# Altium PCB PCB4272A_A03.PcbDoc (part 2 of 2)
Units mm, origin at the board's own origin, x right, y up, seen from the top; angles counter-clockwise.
Board outline 32 x 51 mm, 4 copper layers (Top Layer, Signal Layer 2, Signal Layer 3, Bottom Layer), stack 1.6 mm thick; 110 components, 91 nets, 408 pads, 551 vias.
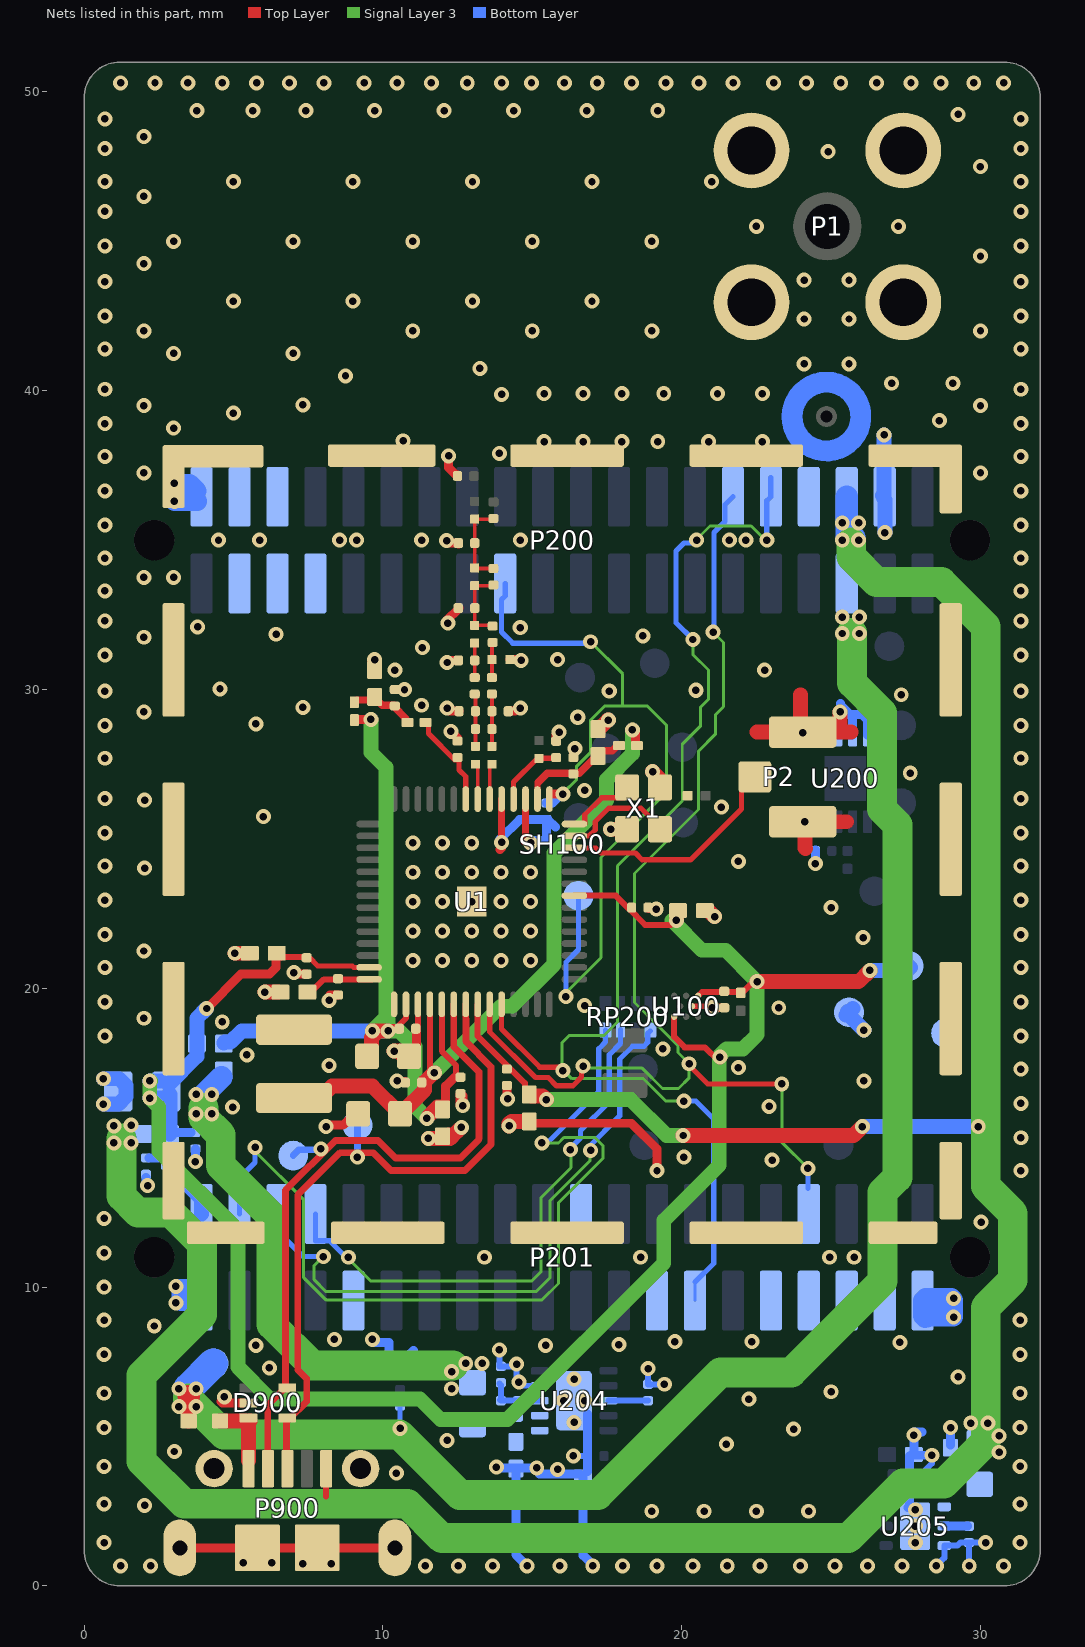
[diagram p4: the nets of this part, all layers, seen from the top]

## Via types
v1: diameter 0.5, hole 0.25, Top Layer to Bottom Layer, tented both sides, 512 vias
v2: diameter 0.508, hole 0.25, Top Layer to Bottom Layer, tented both sides, 37 vias
v3: diameter 0.5/0/0/0.5 (per signal layer), hole 0.25, Top Layer to Bottom Layer, tented both sides, 2 vias

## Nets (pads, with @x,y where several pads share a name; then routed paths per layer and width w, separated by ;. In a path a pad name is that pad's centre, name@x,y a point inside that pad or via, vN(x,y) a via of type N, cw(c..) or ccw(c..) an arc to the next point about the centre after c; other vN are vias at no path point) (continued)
EFR32_PD04: P200.32 P201.27 U1.52 | length 41.7
  Top Layer w0.175: U1.52@13.975,19.465 13.975,18.64 15.253,17.363 v1@15.875,17.363
  Signal Layer 3 w0.1: v1@15.875,17.275 16,17.4 16,18.191 16.234,18.425 17.4,18.425 17.85,18.875 17.85,24.1 20.02,26.27 20.02,28.165 20.625,28.77 20.625,29.4 20.9,29.675 20.9,30.65 20.375,31.175 v2@20.375,31.6 ; v1(16.025,17.25) 16.05,17.25 16.325,16.975 18.725,16.975 19.474,16.226 v2(20.076,16.226) ; v2@20.35,31.675 v2@20.4,31.625 ; v2@20.5,35.025 20.95,35.475 22.325,35.475 22.838,34.963 22.877,35.002 v2(22.851,35.002)
  Bottom Layer w0.1: P201.27@20.445,9.55 P201.27@20.445,10.17
  Bottom Layer w0.175: v2(20.076,16.226) 20.474,16.226 21.075,15.625 ; v2(20.375,31.675) 19.813,32.237 19.813,34.638 20.075,34.9 20.4,34.9 v2(20.5,35) ; P201.27@20.445,10.17 21.078,10.803 21.078,15.625 ; v2@22.975,35.1 22.85,35.1 22.85,36.315 P200.32@22.985,36.45 P200.32@22.985,37.09
EFR32_PD05: P200.30 P201.34 U1.51 | length 38.4
  Top Layer w0.175: U1.51@13.575,19.465 13.575,18.545 15.108,17.013 15.537,17.013 15.812,16.738 16.357,16.738 16.65,17.03 v1@16.65,17.3 ; v1@20.2,17.475 20.875,16.8 v1(23.35,16.8)
  Signal Layer 3 w0.1: v1@16.575,17.35 16.597,17.328 18.678,17.328 19.355,16.651 19.894,16.651 20.251,17.008 v1(20.251,17.476) 19.875,17.852 19.875,18.075 18.421,19.529 18.421,23.846 20.56,25.985 20.56,27.935 21.125,28.5 21.125,29.15 21.4,29.425 21.4,31.575 v2(21.05,31.925) ; v1@23.3,16.75 23.35,16.7 23.35,14.85 v1(24.225,13.975) ; v1@23.3,16.8 v1(23.35,16.8)
  Bottom Layer w0.175: v2@21.083,31.883 21.083,35.258 21.45,35.625 21.45,36.185 P200.30@21.715,36.45 ; v1(24.225,13.975) P201.34@24.228,13.298
  other v1: 16.7,17.4
EFR32_PD06: D900.4 P900.3 TPJ18.1 U1.49 | length 24
  Top Layer w0.22: 12.775,18.9 U1.49@12.775,19.465
  Top Layer w0.23: P900.3@6.845,4.15 6.775,4.22 6.775,5.5 D900.4@6.85,5.575 ; 7.355,6.08 D900.4@6.95,5.675 ; 12.777,18.977 12.777,18.222 13.625,17.374 13.625,14.875 ; 13.624,14.925 13.624,14.777 12.748,13.9 10.277,13.9 9.677,14.5 8.573,14.5 7.15,13.077 7.15,7.25 7.453,6.947 7.453,6.178 D900.4@6.95,5.675 ; D900.4@6.85,5.575 D900.4@6.95,5.675 ; D900.4@6.85,5.575 D900.4@6.95,5.675
  Bottom Layer w0.23: v3(9.15,14.35) TPJ18.1@9.15,15.42
EFR32_PD07: D900.5 P900.2 TPJ19.1 U1.48 | length 22.9
  Top Layer w0.22: 12.375,18.75 U1.48@12.375,19.465
  Top Layer w0.23: P900.2@6.195,4.15 6.15,4.195 6.15,6.05 D900.5@6.725,6.625 ; D900.5@6.745,6.73 6.745,13.245 8.412,14.912 9.838,14.912 10.425,14.325 12.6,14.325 13.2,14.925 ; 12.372,18.962 12.372,18.054 13.219,17.207 13.219,14.975
  Bottom Layer w0.23: TPJ19.1@7,14.4 7.2,14.6 v3@7.85,14.6 ; v3@7.85,14.675 v3@7.925,14.675
  other v3: 7.925,14.625
EFR32_RESET: C207.1 P200.17 TPJ17.1 U1.15 | length 28.3
  Top Layer w0.3: U1.15@15.625,26.5 v2(16.025,26.5)
  Signal Layer 3 w0.1: v2(16.025,26.5) 16.025,26.525 16.487,26.987 16.487,27.433 16.954,27.9 16.954,28.979 17.425,29.45 18.025,29.45 ; v1@16.062,19.788 17.3,21.025 17.3,24.375 19.5,26.575 19.5,28.8 18.85,29.45 18.025,29.45 ; v1(16.95,31.6) 16.95,31.653 16.923,31.627 v1(16.95,31.6) ; v1(16.95,31.6) 18.025,30.525 18.025,29.45
  Bottom Layer w0.175: P200.17@14.095,33.55 14.095,33.13 13.975,33.01 13.975,31.925 14.35,31.55 v1@16.95,31.55 ; v1@16.125,19.75 16.125,20.875 16.55,21.3 TPJ17.1@16.55,23.1
  Bottom Layer w0.3: C207.1@15.475,26.2 15.675,26.2 v2@15.926,26.451
  other v1: 16.125,19.725
GND: C102.2 C103.2 C105.2 C106.2 C107.2 C110.2 C111.2 C112.2 C113.2 C114.2 C115.2 C116.2 C117.2 C118.2 C119.2 C120.2 C121.2 C122.2 C123.2 C124.2 C200.2 C201.2 C203.2 C205.2 C207.2 C253.2 C254.2 C255.2 C257.2 C258.2 C259.2 C260.2 C261.2 CM1.2 CM3.2 CM5.2 CN1.2 CN3.1 CP1.2 CR1.2 D900.2 LP2.1 P1.2 P1.3 P1.4 P1.5 P2.2 P2.3 P200.2 P200.38 P201.1 P201.39 P900.5 P900.6 P900.7 P900.8 P900.9 P900.10 P900.11 R223.1 R246.1 R329.2 SH100.1 TP1.2 TPJ13.1 U1.0 U1.17 U1.19 U1.45 U100.B2 U200.2 U200.3 U200.4 U204.4 U204.11 U205.3 U205.7 X1.2 X1.4 | length 91.9
  Top Layer w0.175: U100.B2@20.35,19.4 U100.B2@20.405,19.399 ; U100.B2@20.405,19.4 20.695,19.4 20.712,19.399 v2@20.875,19.4
  Top Layer w0.2: 8.1,3 P900.5@8.1,3.975 ; C110.2@11.175,18.7 U1.45@11.175,19.465 ; v2@20.875,19.4 v2@20.9,19.375
  Top Layer w0.22: v1@13.961,24.871 v1(13.975,24.886)
  Top Layer w0.23: v1(13.975,24.886) U1.19@13.975,26.335 ; v1@14.775,24.9 U1.17@14.775,26.335
  Top Layer w0.3: P900.8@3.3,1.275 10.125,1.275 P900.9@10.3,1.1 ; v1@4.599,6.2 4.724,6.325 v1(4.7,6.325) ; v1@4.6,6.2 4.575,6.175 4.625,6.125 D900.2@5.5,6.125 ; v1@7.175,20.475 C116.2@7.45,20.475 ; v2(8.1,15.375) 8.15,15.425 8.675,15.425 9.075,15.825 C120.2@9.15,15.825 ; v1@8.225,19.625 8.225,19.775 C122.2@8.5,19.775 ; C106.2@10.4,30 v1@10.775,30 ; v1@10.525,16.875 C121.2@10.75,16.875 ; v1@10.75,30 v1@10.775,30.025 ; C111.2@11.025,17.7 11.125,17.8 C110.2@11.125,18.675 ; v1@11.475,14.95 v1@11.551,14.95 ; v1(11.526,14.976) v1@11.551,14.95 ; v1@11.563,14.938 v1@11.551,14.95 ; C113.2@12.05,14.925 C113.2@12.05,14.975 ; v1(12.136,34.981) 12.217,34.9 12.5,34.9 CM3.2@12.525,34.875 ; v1(12.15,29.375) 12.25,29.275 CN1.2@12.55,29.275 ; v1(12.15,30.905) 12.125,30.93 12.17,30.975 CN3.1@12.525,30.975 ; v1@12.2,32.175 12.125,32.25 12.125,32.3 CM1.2@12.55,32.725 ; v1@12.2,37.725 12.2,37.425 12.45,37.175 CM5.2@12.5,37.175 ; v1(12.275,28.6) 12.5,28.375 C107.2@12.5,28.3 ; v1@12.55,15.2 12.475,15.2 12.2,15.2 C113.2@12.1,15.1 ; v1@12.575,16.075 12.575,16.1 12.6,16.075 v1(12.675,16.075) v1@12.675,16.2 ; v1@12.575,16.175 12.6,16.2 C112.2@12.6,16.475 ; v1@12.575,16.25 C112.2@12.575,16.45 ; v1@12.6,16.125 v1@12.675,16.2 ; C112.2@12.625,16.45 12.675,16.4 v1@12.675,16.2 ; v1@13.925,24.65 13.975,24.7 v1(13.975,24.886) ; v1@14.15,16.35 C118.2@14.15,16.7 ; CP1.2@14.2,29.275 14.425,29.275 v1@14.55,29.4 ; LP2.1@14.25,31 v1@14.575,31 ; v1@14.775,24.9 v1@14.875,24.8 ; C119.2@14.9,15.55 14.965,15.485 18.315,15.485 19.175,14.625 v1(19.175,13.9) ; CR1.2@15.8,28.272 v1@15.8,28.497 ; v1@15.85,28.497 v1@15.85,28.55 ; v1@15.851,28.498 v1@15.851,28.551 ; v1@15.851,28.599 v1@15.851,28.551 ; v1@15.875,28.525 v1@15.9,28.55 ; v1@15.875,28.575 v1@15.851,28.551 ; C103.2@16.375,27.725 v1@16.375,28 ; C114.2@18.9,22.675 19.025,22.675 C114.2@18.95,22.7 ; C124.2@21.425,19.35 21,19.35 21.025,19.375 v2@21.026,19.376 ; v1@11.551,14.95 11.85,14.95 11.876,14.976 C113.2@12,15.1 ; C113.2@12,15.1 C113.2@12,15.05 12.05,15.05 C113.2@12.1,15.1 ; C113.2@12,15.1 C113.2@12.1,15.1 ; v2@21.026,19.376 21.05,19.352 21.081,19.383 21.033,19.383 v2@21.026,19.376
  Top Layer w0.5: v1(5.05,21.175) C117.2@5.5,21.175 ; v1(6.05,19.875) C123.2@6.5,19.875 ; C105.2@9.725,30.65 v1@9.725,30.975 ; v1(10.375,17.9) 10.525,17.9 C111.2@10.65,17.775 ; v1(11.526,14.976) 11.876,14.976 12.251,14.976 12.475,15.2 v1@12.575,15.3 ; v1(14.225,15.4) 14.225,15.475 14.3,15.55 C119.2@14.9,15.55 ; C102.2@17.25,28.7 17.526,28.976 v1(17.551,28.976) ; v2(17.625,25.325) X1.2@18,25.325 ; v2(19.025,27.25) 19.35,26.925 X1.4@19.35,26.6 ; C115.2@20.775,22.6 20.9,22.6 v1(21.1,22.4) ; 22.525,28.575 P2.3@24.05,28.575 ; 23.975,29.825 23.975,28.65 P2.3@24.05,28.575 ; 24.15,24.675 24.125,24.7 P2.2@24.125,25.5 ; P2.2@24.175,25.45 P2.2@24.125,25.5 ; 25.275,28.675 25.3,28.7 v1(25.3,29.25) ; 25.525,25.575 P2.2@24.05,25.575 P2.2@24.125,25.5 ; 25.675,28.575 P2.3@24.05,28.575
  Bottom Layer w0.2: v2@13.85,7.925 13.9,7.875 13.9,7.35 14.475,7.35 14.475,6.9 v1(14.55,6.825) ; v1@14.55,6.775 14.625,6.7 U204.4@15.25,6.7 ; v1@16.275,4.35 C254.2@16.85,4.35 ; v1@18.85,7.225 18.875,7.2 C255.2@18.875,6.75 19.375,6.75 v1@19.4,6.725 ; C261.2@27.6,3.75 27.625,3.75 28.025,3.75 28.375,4.1 v1@28.375,4.3 ; v1(28.525,0.675) 28.79,0.94 U205.3@28.79,1.35 29.225,1.35 29.325,1.45 C259.2@29.615,1.45 ; v1@29.6,0.75 29.615,0.765 C259.2@29.615,1.45 ; v1@30.15,1.425 30.125,1.45 C259.2@29.615,1.45
  Bottom Layer w0.3: v1@2.075,13.55 C201.2@2.075,13.675 ; C203.2@3.725,14.625 3.725,14.175 v1@3.775,14.175 ; v1(9.65,8.25) 9.75,8.15 10.2,8.15 10.2,7.7 R223.1@10.575,7.7 10.85,7.7 11.025,7.875 ; v1@13.925,3.95 v1(15.15,3.95) ; v1@13.925,25 14.575,25.65 C207.2@15.475,25.65 ; C257.2@14.45,3.925 14.45,1.05 v1@14.8,0.7 ; v1@14.85,24.95 15.425,24.95 15.475,25 C207.2@15.475,25.65 ; v1@15.15,3.85 15.25,3.75 16.6,3.75 C253.2@16.7,3.65 16.7,1.025 v1@17,0.725 ; 15.775,25.4 15.525,25.65 C207.2@15.475,25.65 ; C253.2@16.85,3.825 C254.2@16.85,4.35 U204.11@16.85,5.75 ; v1(17.025,0.675) v1@17.025,0.7 ; v1(24.475,24.175) C200.2@24.475,24.625 ; U200.2@25.225,28.475 25.225,28.975 25.413,29.162 25.638,29.162 ; 25.312,29.538 25.312,29.488 25.638,29.162 ; U200.3@25.725,28.475 25.725,29.075 25.638,29.162 ; U200.4@26.225,28.475 26.225,28.975 26.037,29.162 25.638,29.162 ; U205.7@27.575,2.625 27.625,2.675 27.625,3.75 27.625,4.35 27.65,4.375 27.675,4.35 27.7,4.375 v1(28.375,4.375) ; C260.2@27.775,4.5 27.775,5.15 28.05,5.15 ; C258.2@29,4.725 v1(29,5.3)
  Bottom Layer w0.5: v1(0.65,16.125) 1.15,16.125 1.4,16.375 1.4,16.75 1.175,16.975 v1(0.65,16.975) ; TPJ13.1@25.5,19.1 TPJ13.1@25.6,19.1 ; TPJ13.1@25.55,19.225 25.6,19.175 TPJ13.1@25.6,19.1 ; v1(26.1,18.6) TPJ13.1@25.6,19.1 ; P200.38@26.725,36.5 26.775,36.55 v1(26.775,38.525) ; P200.38@26.775,36.375 26.8,36.35 v1(26.8,35.25)
  Bottom Layer w0.508: TPJ13.1@25.6,19.2 TPJ13.1@25.725,19.325
  Bottom Layer w0.635: v1(3.025,36.3) 3.796,36.3 3.798,36.302 P200.2@3.8,36.3 ; v1@3.1,36.9 3.535,36.9 P200.2@3.785,36.65 ; P201.39@28.065,9.55 28.065,9.035 28.15,8.95 28.2,9 28.225,8.975 28.25,9 v1(29.1,9) 29.1,9.575 v1@29.025,9.65 ; P201.39@28.065,9.55 28.165,9.65 v1@29.025,9.65 ; P201.39@28.065,9.55 28.925,9.55 v1@29.025,9.65 ; v1@3.25,9.525 3.935,9.525 3.935,9.95 3.25,9.95 v1@3.25,9.525
  other v1: 1.225,0.675 2.225,0.675 11.425,0.675 12.525,0.675 13.675,0.675 14.825,0.675 15.925,0.675 18.025,0.675 19.175,0.675 20.375,0.675 21.525,0.675 22.625,0.675 23.975,0.675 25.125,0.675 26.225,0.675 27.375,0.675 29.625,0.675 30.775,0.675 7.325,0.75 8.275,0.75 5.325,0.775 6.275,0.775 0.675,1.45 27.825,1.45 30.175,1.45 31.325,1.45 27.825,2 19,2.5 20.75,2.5 22.5,2.5 24.25,2.5 27.825,2.55 2.025,2.7 0.675,2.75 31.325,2.75 10.45,3.775 15.85,3.9 13.8,3.975 0.675,4 31.325,4 16.375,4.35 3.025,4.5 21.5,4.75 12.15,4.875 27.775,5.05 23.75,5.25 0.675,5.3 31.325,5.3 16.4,5.475 16.05,6.2 16.75,6.2 22.25,6.25 0.675,6.45 31.325,6.45 25,6.5 19.425,6.75 16.4,6.925 29.25,7 18.875,7.275 6.2,7.3 14.475,7.425 0.675,7.75 31.325,7.75 5.75,8.05 15.45,8.05 17.9,8.075 27.3,8.15 19.775,8.175 22.35,8.175 8.375,8.25 2.35,8.7 0.675,8.9 31.325,8.9 3.075,9.475 29.1,9.625 0.675,10 3.075,10.025 13.4,11 18.625,11 24.95,11 25.775,11 0.675,11.15 30.025,12.175 0.675,12.3 2.125,13.4 31.35,13.9 3.725,14.2 23.025,14.25 20.075,14.35 31.35,15 12.625,15.35 4.975,16.025 22.925,16.05 31.35,16.15 14.175,16.3 10.475,16.9 26.101,16.902 31.35,17.3 8.2,17.425 5.45,17.775 0.7,18.4 31.35,18.4 4.625,18.876 2,19 23.25,19.35 0.7,19.55 31.35,19.55 8.2,19.6 7.025,20.525 0.7,20.7 31.35,20.7 11.004,20.929 11.99,20.929 12.975,20.929 13.961,20.929 14.946,20.929 2,21.25 26.075,21.7 0.7,21.8 31.35,21.8 11.004,21.915 11.99,21.915 12.975,21.915 13.961,21.915 14.946,21.915 19.15,22.651 25.001,22.702 11.004,22.9 11.99,22.9 12.975,22.9 13.961,22.9 14.946,22.9 0.7,22.95 31.35,22.95 11.004,23.885 11.99,23.885 12.975,23.885 13.961,23.885 14.946,23.885 2.025,24.025 0.7,24.1 31.35,24.1 11.004,24.871 11.99,24.871 12.975,24.871 14.946,24.871 0.7,25.2 31.35,25.2 6,25.75 2.025,26.3 0.7,26.35 31.35,26.35 16.751,26.626 27.65,27.2 0.7,27.7 31.35,27.7 16.425,28.025 15.9,28.572 0.7,28.8 31.35,28.8 5.75,28.85 2,29.25 14.6,29.375 7.325,29.4 11.3,29.475 27.35,29.825 0.7,29.95 31.35,29.95 10.725,30 4.55,30.025 10.4,30.65 22.775,30.65 14.625,30.975 9.725,31 0.7,31.15 31.35,31.15 11.325,31.4 2,31.75 6.425,31.85 3.8,32.1 12.175,32.225 0.7,32.3 31.35,32.3 0.7,33.3 31.35,33.3 2.001,33.752 3,33.75 0.7,34.4 31.35,34.4 4.5,35 5.875,35 8.55,35 9.125,35 11.3,35 14.6,35 21.6,35 22.15,35 0.7,35.5 31.35,35.5 0.7,36.65 31.35,36.65 3.025,36.9 2.001,37.252 30.001,37.252 0.7,37.8 31.35,37.8 12.2,37.82 13.9,37.9 15.4,38.3 16.7,38.3 18,38.3 19.2,38.3 20.9,38.3 22.7,38.3 10.675,38.325 3.001,38.752 0.7,38.9 31.35,38.9 28.625,39 5,39.25 2.001,39.502 30.001,39.502 7.325,39.525 13.975,39.875 15.4,39.9 16.7,39.9 18,39.9 19.4,39.9 21.2,39.9 22.7,39.9 0.7,40.05 31.35,40.05 27.025,40.25 29.075,40.25 8.75,40.5 13.25,40.75 24.1,40.9 25.6,40.9 3,41.25 7,41.25 0.7,41.4 31.35,41.4 2.001,42.002 11,42 15,42 19.001,42.002 30.001,42.002 24.1,42.4 25.6,42.4 0.7,42.5 31.35,42.5 5,43 9,43 13,43 17,43 0.7,43.65 31.35,43.65 24.1,43.7 25.6,43.7 2.001,44.252 30.001,44.502 0.7,44.85 31.35,44.85 3,45 7,45 11,45 15,45 19,45 22.5,45.5 27.25,45.5 0.7,46 31.35,46 2.001,46.502 0.7,47 5,47 9,47 13,47 17,47 21,47 31.35,47 30,47.5 24.9,48 0.7,48.1 31.35,48.1 2.001,48.502 0.7,49.1 31.35,49.1 29.25,49.25 3.775,49.375 5.65,49.375 7.425,49.375 9.725,49.375 12.05,49.375 14.375,49.375 16.825,49.375 19.2,49.375 1.225,50.3 2.375,50.3 3.475,50.3 4.625,50.3 5.775,50.3 6.875,50.3 8.025,50.3 9.375,50.3 10.475,50.3 11.625,50.3 12.825,50.3 13.975,50.3 14.975,50.3 16.075,50.3 17.175,50.3 18.325,50.3 19.475,50.3 20.575,50.3 21.725,50.3 23.075,50.3 24.175,50.3 25.325,50.3 26.525,50.3 27.675,50.3 28.675,50.3 29.775,50.3 30.775,50.3
  other v2: 13.9,7.9 21.9,17.35 19.375,17.975 21.025,19.35 16.75,19.425 21.9,24.25 24.125,25.575 21.33,26.067 24.05,28.55 16.525,29.075 17.575,29.95 20.475,29.975 15.85,31 18.702,31.796 14.6,32.075
N17556723: C122.1 C123.1 U1.42 | length 2.2
  Top Layer w0.2: C123.1@7.6,19.95 7.675,19.95 8.025,20.3 U1.42@9.54,20.3 U1.42@9.64,20.3
N17556727: L101.1 U1.43
N17618697: P2.1 U1.12 | length 7.4
  Top Layer w0.175: U1.12@16.41,24.7 17.125,24.7 17.3,24.525 18.456,24.525 18.681,24.3 20.3,24.3 22,26 P2.1@22,26.925
N17758206: CM2.2 CM3.1 CM4.1 LM1.2 LM2.1 | length 2.9
  Top Layer w0.1: LM2.1@13.075,35.725 LM2.1@13.1,35.7 ; CM2.2@13.675,34.05 CM2.2@13.7,34.075
  Top Layer w0.125: LM2.1@13.075,35.725 LM2.1@13.075,35.7 CM3.1@13.075,34.9 LM1.2@13.075,34.075 13.075,34.05 CM2.2@13.675,34.05 ; LM2.1@13.1,35.7 CM4.1@13.675,35.7
N17758241: CM1.1 CM2.1 CP3.1 LM1.1 LN2.2 | length 2.6
  Top Layer w0.1: LM1.1@13.075,33.5 LM1.1@13.1,33.475
  Top Layer w0.125: LM1.1@13.075,33.5 LM1.1@13.075,33.475 CM1.1@13.075,32.725 LN2.2@13.075,32.15 CP3.1@13.675,32.15 ; LM1.1@13.1,33.475 CM2.1@13.7,33.475
N17758340: LN1.1 U1.21 | length 1.2
  Top Layer w0.125: U1.21@13.175,26.335 LN1.1@13.175,27.55
N17758346: LP1.1 U1.20 | length 1.1
  Top Layer w0.1: LP1.1@13.575,27.4 LP1.1@13.625,27.45
  Top Layer w0.125: U1.20@13.575,26.335 LP1.1@13.575,27.4
N17758372: C102.1 C103.1 L102.2 U1.16 | length 3.6
  Top Layer w0.2: U1.16@15.175,26.335 15.175,26.875
  Top Layer w0.25: 15.2,26.9 15.5,27.2 16.575,27.2 17.125,27.75 C102.1@17.125,27.825 ; C102.1@17.25,27.925 17.275,27.95 17.675,27.95 17.825,28.1 L102.2@17.925,28.1
N17758436: C107.1 L105.2 U1.22 | length 3
  Top Layer w0.175: L105.2@11.525,28.775 11.525,28.526 12.401,27.65 12.5,27.65 12.55,27.6 12.55,27.31 12.775,27.085 U1.22@12.775,26.335
N17758469: C105.1 C106.1 L103.2 L105.1 | length 2.1
  Top Layer w0.25: L103.2@9.05,29.575 9.125,29.65 C105.1@9.725,29.65 ; C105.1@9.775,29.675 9.975,29.475 10.375,29.475 C106.1@10.4,29.45 ; C106.1@10.375,29.425 10.775,29.025 L105.1@10.775,28.885
N17758534: U1.13 X1.3 | length 3.7
  Top Layer w0.175: U1.13@16.41,25.1 U1.13@16.7,25.1 ; X1.3@19.125,25.475 19.125,25.537 18.637,26.025 17.55,26.025 17.109,25.583 17.109,25.308 16.9,25.1 ; U1.13@16.7,25.1 16.9,25.1 ; U1.13@16.7,25.1 16.9,25.1
N17758549: U1.14 X1.1 | length 2.3
  Top Layer w0.175: U1.14@16.375,25.5 U1.14@16.41,25.5 16.758,25.5 16.758,25.808 17.325,26.375 18.075,26.375 X1.1@18.1,26.4
N17758602: CR1.1 LR1.1 U1.18 | length 2.4
  Top Layer w0.175: U1.18@14.375,26.207 14.375,26.9 15.175,27.7 15.753,27.7 CR1.1@15.775,27.722
N17776329: CD1.1 CN1.1 CN2.1 LN1.2 | length 1.8
  Top Layer w0.1: CN2.1@13.075,29.85 CN2.1@13.1,29.825
  Top Layer w0.125: LN1.2@13.1,28.1 CD1.1@13.1,28.675 CN2.1@13.1,29.825
N17776334: CD1.2 CP1.1 CP2.2 LP1.2 | length 1.7
  Top Layer w0.125: LP1.2@13.65,28.1 CD1.2@13.65,28.675 CP2.2@13.65,29.85
N17776576: CP2.1 CP3.2 LP2.2 | length 1.2
  Top Layer w0.1: CP3.2@13.65,31.575 CP3.2@13.675,31.6
  Top Layer w0.125: CP2.1@13.65,30.4 LP2.2@13.65,31 CP3.2@13.65,31.575
N17777945: CN2.2 CN3.2 LN2.1 | length 1.2
  Top Layer w0.125: CN2.2@13.075,30.4 CN3.2@13.075,30.975 LN2.1@13.075,31.55
N17782103: D900.3 L901.1 P900.1 | length 2.2
  Top Layer w0.5: L901.1@4.55,5.525 D900.3@5.4,5.525 ; P900.1@5.5,4.195 5.5,5.475 D900.3@5.55,5.525
N17783001: C256.1 C257.1 R245.2 R247.1 U204.1 U204.2
N17783095: C256.2 R245.1 R246.2 U204.3 | length 1.9
  Bottom Layer w0.2: R246.2@13.9,6.775 13.95,6.725 13.95,6.25 R245.1@13.925,6.225 ; R245.1@13.95,6.2 C256.2@14.525,6.2 U204.3@15.25,6.2
N17783110: C258.1 R248.1 U205.1
N17783132: C255.1 U204.8 | length 1.3
  Bottom Layer w0.2: U204.8@17.55,6.2 17.554,6.204 18.871,6.204 C255.1@18.875,6.2
N17783286: C259.1 U205.2 | length 0.8
  Bottom Layer w0.3: U205.2@28.79,2 C259.1@29.565,2
USB_VBUS: L901.2 P200.35 R224.2 TPJ20.1 | length 53.2
  Top Layer w0.5: 3.475,6.4 3.5,6.375 3.5,6.35 L901.2@3.5,5.525
  Signal Layer 3 w1: 3.475,6.275 4.675,5.075 10.55,5.075 12.575,3.05 17.2,3.05 21.3,7.15 23.675,7.15 26.262,9.737 26.725,10.2 26.725,13.175 27.225,13.675 27.225,25.475 26.7,26 26.7,29.225 25.7,30.225 25.7,31.9
  Bottom Layer w0.175: v2(10.575,5.275) R224.2@10.575,6.025
  Bottom Layer w1: 3.5,6.325 3.5,6.625 TPJ20.1@4.325,7.45
  other v1: 3.175,6 3.75,6 3.175,6.6 3.75,6.6 25.375,31.875 25.95,31.875 25.375,32.425 25.95,32.425
USB_VREG: C118.1 C119.1 P200.36 R202.2 R248.2 U1.50 | length 98.8
  Top Layer w0.2: U1.50@13.175,19.465 13.175,18.4 14.75,16.825 C119.1@14.75,16.55
  Top Layer w0.5: C119.1@14.975,16.4 15.35,16.4 v1(15.475,16.275) ; v1(20.051,15.076) 25.751,15.076 v1(26.05,15.375)
  Signal Layer 3 w0.5: v1(15.475,16.275) 18.3,16.275 19.499,15.076 v1(20.051,15.076)
  Signal Layer 3 w1: 1.25,14.975 1.25,13.05 1.8,12.5 2.9,12.5 3.95,11.45 3.95,9.075 1.925,7.05 1.925,4.175 3.35,2.75 10.825,2.75 11.975,1.6 25.575,1.6 27.4,3.425 28.775,3.425 30.175,4.825 30.175,6.375 ; 25.676,34.927 25.674,34.453 26.518,33.604 28.695,33.596 30.175,32.106 30.175,13.375 31.081,12.469 31.081,10.231 30.175,9.325 30.175,6.4
  Bottom Layer w0.5: v1(26.05,15.375) v1(29.925,15.375)
  Bottom Layer w0.75: v1@25.525,35.1 v1@25.775,35.1 ; v1@25.525,35.12 P200.36@25.525,36.45
  other v1: 30.625,4.475 30.625,5.025 29.675,5.45 30.25,5.45 1,14.825 1.575,14.825 1,15.4 1.575,15.425 25.375,35 25.925,35 25.375,35.575 25.925,35.575
VDCDC: C120.1 C121.1 L101.2 L102.1 U1.46 | length 23
  Top Layer w0.2: 11.43,17.03 11.325,16.925 11.575,17.175 U1.46@11.575,19.465
  Top Layer w0.3: 11.3,16.5 C121.1@11.3,16.85 ; v1@18.45,28.65 18.45,28.175 L102.1@18.5,28.125
  Top Layer w0.5: L101.2@7.95,16.375 8.3,16.725 9.65,16.725 C120.1@10.575,15.8 ; C120.1@10.675,15.875 11.4,16.6 11.4,16.875 11.7,17.175 v1(11.725,17.175)
  Signal Layer 3 w0.5: v1(11.725,17.175) 13.95,19.4 14.325,19.4 15.725,20.8 15.725,24.525 17.484,26.284 17.484,26.984 18.351,27.851 v1(18.351,28.651) v1(18.351,28.651)
VDD: C110.1 C111.1 C112.1 C113.1 L103.1 R210.2 R211.2 U1.44 U1.47 | length 29.2
  Top Layer w0.2: C110.1@10.475,18.65 10.475,18.7 10.775,19 U1.44@10.775,19.465 ; U1.47@11.975,19.435 11.975,17.9 12.45,17.425 C112.1@12.45,17.025 ; U1.47@11.975,19.465 U1.47@11.975,19.48
  Top Layer w0.3: L103.1@9.05,28.975 9.074,28.951 9.122,29 v2(9.6,29) v2@9.575,28.975 ; v1@10.1,18.575 10.175,18.65 C110.1@10.475,18.65 ; C113.1@12,15.95 12.1,16.05 12.1,16.725 12.4,17.025 12.45,17.025 C112.1@12.55,17.025
  Top Layer w0.5: C111.1@9.475,17.725 9.625,17.875 9.625,18.35 v1@9.85,18.575 ; v1(9.65,18.575) 10.1,18.575 v1(10.175,18.575) ; v1@11.55,15.75 11.825,16.025 C113.1@11.9,16.025
  Signal Layer 3 w0.5: v2(9.6,29) 9.6,27.9 10.1,27.4 10.1,19.025 ; 10.1,18.925 10.1,19.025 ; v1@11.45,15.675 11.075,16.05 11.075,18.05 10.55,18.575 v1(10.175,18.575) ; 10.1,19.025 10.175,18.95 v1(10.175,18.575) ; 10.1,19.025 v1(9.65,18.575) v1(10.175,18.575)
  Bottom Layer w0.5: R211.2@4.675,18.175 4.701,18.201 4.905,18.201 5.279,18.575 v1(9.65,18.575) v1(10.175,18.575)
  other v1: 11.476,15.651
VLDO_3V6: R211.1 R247.2 | length 15.7
  Signal Layer 3 w1: 4,16 4,15.675 4.575,15.1 4.575,14.075 6.275,12.375 6.275,8.75 7.65,7.375 v1@12.35,7.375
  Bottom Layer w0.75: 4,16.25 4.025,16.25 ; 4,16.425 R211.1@4.6,17.025
  other v1: 12.3,6.6 12.3,7.175 12.775,7.45 13.325,7.45 3.75,15.8 4.275,15.8 3.75,16.45 4.275,16.45
VMCU: C114.1 C115.1 C116.1 C117.1 C124.1 C203.1 C205.1 R103.2 R201.1 R202.1 R210.1 TPJ11.1 U1.8 U1.41 U100.A1 U100.E3 | length 69.9
  Top Layer w0.175: C116.1@7.562,21.012 7.824,20.75 8.975,20.75 9.025,20.7 U1.41@9.54,20.7
  Top Layer w0.2: C117.1@6.475,21.1 6.525,21.05 C117.1@6.575,21.05 ; C117.1@6.55,21.075 C117.1@6.575,21.05 ; C117.1@6.6,21.025 C117.1@6.575,21.05 ; C116.1@7.45,21.025 7.425,21.05 C117.1@6.575,21.05 ; U1.8@16.41,23.1 17.8,23.1 C114.1@18.2,22.7 ; C114.1@18.225,22.675 18.774,22.126 ; 18.925,22.125 18.775,22.125 18.774,22.126 ; v1@19.648,22.126 18.774,22.126 ; U100.E3@19.75,19.025 19.75,18.375 20.1,18.025 20.775,18.025 21.25,17.55 21.306,17.55 21.331,17.575 21.276,17.63 v1(21.276,17.701) ; v1@19.847,22.15 v1@19.9,22.15 ; U100.A1@20.55,19.75 20.679,19.879 R103.2@21.871,19.879 ; R103.2@22,19.825 22.4,20.225 v2(22.525,20.225)
  Top Layer w0.3: v1(4.1,19.325) 5.25,20.475 6.2,20.475 6.425,20.7 6.425,21.1 C117.1@6.45,21.125
  Top Layer w0.5: v1@19.825,22.3 19.825,22.525 C115.1@19.875,22.575 ; v2(22.525,20.225) v2(22.525,20.225) 25.924,20.226 25.925,20.225 v1(26.3,20.6)
  Signal Layer 3 w0.5: v1@2.224,16.9 v1(2.2,16.9) v1(2.2,16.325) 2.5,16.025 2.5,14.55 5.15,11.9 5.15,7.325 6.225,6.25 11.25,6.25 11.925,5.575 14.175,5.575 19.4,10.8 19.4,12.225 21.259,14.084 21.259,17.734 21.5,17.975 22.05,17.975 22.526,18.451 v2(22.525,20.225) ; v1@19.676,22.274 20.675,21.275 21.475,21.275 v2(22.525,20.225) ; v1@19.826,22.249 v1(19.826,22.276)
  Bottom Layer w0.3: R201.1@2.9,15.225 2.95,15.175 C203.1@3.575,15.175
  Bottom Layer w0.5: v1(2.2,16.325) 2.825,16.325 C205.1@2.85,16.3 ; v1(2.2,16.9) C205.1@2.575,16.9 ; C205.1@2.825,16.775 3.775,17.725 R210.1@3.775,18.15 3.775,19 v1(4.1,19.325) ; C205.1@2.85,16.475 2.875,16.45 R201.1@2.875,15.125
  Bottom Layer w0.508: v1(26.3,20.6) 27.2,20.6 27.375,20.775 TPJ11.1@27.5,20.65 ; TPJ11.1@27.6,20.75 TPJ11.1@27.55,20.7 ; TPJ11.1@27.65,20.7 27.6,20.65 TPJ11.1@27.55,20.7 ; TPJ11.1@27.5,20.65 TPJ11.1@27.55,20.7 ; TPJ11.1@27.5,20.65 TPJ11.1@27.55,20.7
VMCU_IN: C201.1 P201.2 R201.2 | length 2.9
  Bottom Layer w0.3: C201.1@2.175,14.325 2.925,14.325 R201.2@2.825,14.225
  Bottom Layer w0.5: R201.2@2.875,14 3.935,12.94 P201.2@3.935,12.45
VRF: TPJ9.1
WSTK_F21: P200.34
WSTK_P1: P201.4 RP200.8 | length 28.6
  Signal Layer 3 w0.1: v1@5.75,14.525 7.35,12.925 7.35,10.317 8.092,9.575 15.325,9.575 15.875,10.125 15.875,12.825 17.375,14.325 17.375,14.725 17.095,15.005 16.055,15.005 15.875,14.825 15.45,14.825 v1@15.425,14.8
  Bottom Layer w0.175: P201.4@5.205,12.45 5.205,13.655 5.7,14.15 5.725,14.176 v1(5.725,14.675) ; v1@5.7,14.601 5.72,14.621 5.72,14.65 v1@5.7,14.65 ; v1(15.326,14.826) 15.449,14.826 15.475,14.8 17.225,16.55 17.225,17.975 17.45,18.2 RP200.8@17.45,18.6
WSTK_P3: P201.6 RP200.5 | length 21.6
  Signal Layer 3 w0.1: v1@7.825,11.05 7.925,10.95 7.7,10.725 7.7,10.25 8.1,9.85 15.125,9.85 15.6,10.325 15.6,12.9 16.925,14.225 16.925,14.55 16.9,14.575 v1(16.95,14.575) v1@16.975,14.575
  Bottom Layer w0.175: P201.6@6.475,12.45 6.475,11.875 7.325,11.025 v1(8.009,11.025) ; v1@16.875,14.6 16.875,14.675 17.925,15.725 17.925,17.625 18.363,18.063 18.738,18.063 18.863,18.188 18.863,18.488 RP200.5@18.95,18.575
WSTK_P5: P201.8 RP200.7 | length 18.5
  Signal Layer 3 w0.1: v1(8.85,11) 8.85,10.95 9.6,10.2 14.975,10.2 15.3,10.525 15.3,13 16.3,14 v1@16.3,14.605
  Bottom Layer w0.175: P201.8@7.745,12.45 7.745,11.555 7.75,11.55 8.225,11.55 8.225,11.542 8.383,11.385 8.692,11.075 v1@8.975,11.075 ; v1@16.25,14.625 16.612,14.987 16.612,15.237 17.575,16.2 17.575,17.775 17.95,18.15 RP200.7@17.95,18.6 RP200.7@17.95,18.625
  other v1: 16.275,14.605
WSTK_P6: P201.9
WSTK_P19: P201.22
WSTK_P22: P201.25
WSTK_P28: P201.31
WSTK_P30: P201.33
WSTK_P32: P201.35
WSTK_P34: P201.37
WSTK_P36: P200.3
WSTK_P37: P200.4
WSTK_P38: P200.5
WSTK_P39: P200.6
WSTK_P40: P200.7
pads on no net: D900.1 P200.M1 P200.M2 P201.40 P201.M1 P201.M2 P900.4 RP200.3 RP200.6 U100.C1 U200.9 U204. U204.5 U205. U205.5

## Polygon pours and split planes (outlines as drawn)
GND on Signal Layer 2 "GND_L2" (solid, remove dead copper, pour order 48): 0,0 0,51 32,51 32,0
GND on Top Layer "GND_L1" (solid, remove dead copper, pour order 56): 0,0 0,51 32,51 32,0
GND on Signal Layer 3 "GND_L3" (solid, remove dead copper, pour order 52): 0,0 0,51 32,51 32,0
GND on Bottom Layer "GND_L4" (solid, remove dead copper, pour order 54): 0,0 0,51 32,51 32,0

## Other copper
Top Layer:
  rectangle net GND: 8.55,15.375 9.05,16.225
  pour cut-out: 17.125,28.975 ccw(c17.548,28.973) 17.55,28.55 ccw(c17.548,28.977) 17.975,28.975 ccw(c17.552,28.977) 17.55,29.4 ccw(c17.552,28.973)
  pour cut-out: 11.711,34.981 ccw(c12.134,34.979) 12.136,34.556 ccw(c12.134,34.983) 12.561,34.981 ccw(c12.138,34.983) 12.136,35.406 ccw(c12.138,34.98)
  pour cut-out: 24.05,39.125 ccw(c24.868,39.143) 24.85,38.325 ccw(c24.794,39.181) 25.65,39.125 ccw(c24.795,39.096) 24.85,39.95 ccw(c24.857,39.143)
  pour cut-out: 9.3,31.013 ccw(c9.723,31.011) 9.725,30.588 ccw(c9.723,31.014) 10.15,31.013 ccw(c9.727,31.014) 9.725,31.438 ccw(c9.727,31.011)
  pour cut-out: 11.768,37.838 ccw(c12.191,37.836) 12.193,37.413 ccw(c12.191,37.84) 12.618,37.838 ccw(c12.195,37.84) 12.193,38.263 ccw(c12.195,37.836)
  pour cut-out: 11.725,29.375 ccw(c12.148,29.373) 12.15,28.95 ccw(c12.148,29.377) 12.575,29.375 ccw(c12.152,29.377) 12.15,29.8 ccw(c12.152,29.373)
  pour cut-out: 10.3,30 ccw(c10.723,29.998) 10.725,29.575 ccw(c10.723,30.002) 11.15,30 ccw(c10.727,30.002) 10.725,30.425 ccw(c10.727,29.998)
  pour cut-out: 15.475,28.572 ccw(c15.898,28.571) 15.9,28.147 ccw(c15.898,28.574) 16.325,28.572 ccw(c15.902,28.574) 15.9,28.997 ccw(c15.902,28.571)
  pour cut-out: 16,28.025 ccw(c16.423,28.023) 16.425,27.6 ccw(c16.423,28.027) 16.85,28.025 ccw(c16.427,28.027) 16.425,28.45 ccw(c16.427,28.023)
  pour cut-out: 23.256,45.461 ccw(c24.869,45.461) 24.869,43.848 ccw(c24.836,45.494) 26.481,45.527 ccw(c24.902,45.528) 24.902,47.107 ccw(c24.902,45.461)
  pour cut-out: 8.736,14.35 ccw(c9.15,14.35) 9.15,13.936 ccw(c9.15,14.35) 9.564,14.35 ccw(c9.15,14.35) 9.15,14.764 ccw(c9.15,14.35)
  pour cut-out: 7.511,14.625 ccw(c7.925,14.625) 7.925,14.211 ccw(c7.925,14.625) 8.339,14.625 ccw(c7.925,14.625) 7.925,15.039 ccw(c7.925,14.625)
  pour cut-out: 11.85,28.6 ccw(c12.273,28.598) 12.275,28.175 ccw(c12.273,28.602) 12.7,28.6 ccw(c12.277,28.602) 12.275,29.025 ccw(c12.277,28.598)
  pour cut-out: 14.175,29.375 ccw(c14.598,29.373) 14.6,28.95 ccw(c14.598,29.377) 15.025,29.375 ccw(c14.602,29.377) 14.6,29.8 ccw(c14.602,29.373)
  pour cut-out: 14.212,30.982 ccw(c14.635,30.98) 14.637,30.557 ccw(c14.635,30.984) 15.062,30.982 ccw(c14.639,30.984) 14.637,31.407 ccw(c14.639,30.98)
  pour cut-out: 11.725,30.905 ccw(c12.148,30.903) 12.15,30.48 ccw(c12.148,30.907) 12.575,30.905 ccw(c12.152,30.907) 12.15,31.33 ccw(c12.152,30.903)
  pour cut-out: 11.75,32.225 ccw(c12.173,32.223) 12.175,31.8 ccw(c12.173,32.227) 12.6,32.225 ccw(c12.177,32.227) 12.175,32.65 ccw(c12.177,32.223)
  region net GND: 19.65,27.15 20.25,26.55 20.25,26.3 19.575,26.3 19.575,27.15
  region net N17556727: 7.337,18.125 7.337,19.125 8.475,19.125 9.225,19.875 10.375,19.875 10.375,19.05 9.425,19.05 8.5,18.125
  pour cut-out: 17.225,25.188 17.225,25.6 17.625,26 17.625,27.15 17.825,27.35 18.425,27.35 18.75,27.675 19.525,27.675 20.5,26.7 20.5,26.175 19.85,25.525 19.85,24.8 19.75,24.7 17.713,24.7
  region net EFR32_PD06: 9.725,14.575 9.725,14.6 9.175,14.6 8.55,14.6 9,14.15 9.3,14.15
  region net EFR32_PD07: 7.675,14.65 7.675,14.15 8.4,14.875 7.9,14.875
  region net USB_VBUS: 3.85,6.85 3.075,6.85 2.925,6.7 2.925,5.9 3.225,5.6 3.7,5.6 4,5.9 4,6.7
  pour cut-out: 14.125,37.1 13.55,37.675 12.055,37.675 11.953,37.573 11.953,31.93 11.6,31.577 11.6,25.473 15.25,25.473 15.25,31.004 14.125,32.099
Signal Layer 2:
  pour cut-out: 24.05,39.125 ccw(c24.868,39.143) 24.85,38.325 ccw(c24.794,39.181) 25.65,39.125 ccw(c24.795,39.096) 24.85,39.95 ccw(c24.857,39.143)
  pour cut-out: 23.256,45.461 ccw(c24.869,45.461) 24.869,43.848 ccw(c24.836,45.494) 26.481,45.527 ccw(c24.902,45.528) 24.902,47.107 ccw(c24.902,45.461)
  pour cut-out: 8.736,14.35 ccw(c9.15,14.35) 9.15,13.936 ccw(c9.15,14.35) 9.564,14.35 ccw(c9.15,14.35) 9.15,14.764 ccw(c9.15,14.35)
  pour cut-out: 7.511,14.625 ccw(c7.925,14.625) 7.925,14.211 ccw(c7.925,14.625) 8.339,14.625 ccw(c7.925,14.625) 7.925,15.039 ccw(c7.925,14.625)
  pour cut-out: 23.05,28.05 23.05,26.1 25.05,26.1 25.05,28.05
Signal Layer 3:
  pour cut-out: 24.05,39.125 ccw(c24.868,39.143) 24.85,38.325 ccw(c24.794,39.181) 25.65,39.125 ccw(c24.795,39.096) 24.85,39.95 ccw(c24.857,39.143)
  pour cut-out: 23.256,45.461 ccw(c24.869,45.461) 24.869,43.848 ccw(c24.836,45.494) 26.481,45.527 ccw(c24.902,45.528) 24.902,47.107 ccw(c24.902,45.461)
  pour cut-out: 8.736,14.35 ccw(c9.15,14.35) 9.15,13.936 ccw(c9.15,14.35) 9.564,14.35 ccw(c9.15,14.35) 9.15,14.764 ccw(c9.15,14.35)
  pour cut-out: 7.511,14.625 ccw(c7.925,14.625) 7.925,14.211 ccw(c7.925,14.625) 8.339,14.625 ccw(c7.925,14.625) 7.925,15.039 ccw(c7.925,14.625)
  region net 5V: 27,6.15 26.225,6.15 26.075,6 26.075,5.2 26.225,5.05 27,5.05 27.15,5.2 27.15,6
  region net 5V: 20.45,4.225 19.675,4.225 19.525,4.075 19.525,3.275 19.675,3.125 20.45,3.125 20.6,3.275 20.6,4.075
  region net 5V: 27.9,31.35 28.025,31.225 28.025,30.35 27.975,30.3 27.075,30.3 26.95,30.425 26.95,31.2 27.1,31.35
  region net USB_VBUS: 26.05,32.7 26.2,32.55 26.2,31.7 25.875,31.375 25.525,31.375 25.125,31.775 25.125,32.55 25.275,32.7
  region net USB_VREG: 25.1,35.75 25.25,35.9 26.025,35.9 26.175,35.75 26.175,34.875 26.025,34.725 25.275,34.725 25.1,34.9
  region net VLDO_3V6: 4.525,15.672 4.525,16.55 4.378,16.697 3.725,16.697 3.5,16.472 3.5,15.728 3.675,15.553 4.406,15.553
  region net USB_VREG: 0.75,15.512 0.75,14.738 1,14.487 1.6,14.487 1.85,14.738 1.85,15.512 1.7,15.662 0.9,15.662
  region net USB_VBUS: 3.85,6.85 3.075,6.85 2.925,6.7 2.925,5.9 3.075,5.75 3.85,5.75 4,5.9 4,6.7
  region net USB_VREG: 29.425,5.55 29.575,5.7 30.375,5.7 30.875,5.2 30.875,4.525 30.575,4.225 29.775,4.225 29.425,4.575
  region net VLDO_3V6: 13.375,7.125 12.6,6.35 12.2,6.35 12.05,6.5 12.05,7.625 12.3,7.875 13.25,7.875 13.575,7.55 13.575,7.325
Bottom Layer:
  rectangle net GND: 27.325,0.775 28.325,3.175
  rectangle net GND: 15.8,4.85 17,7.5
  pour cut-out: 23.256,45.461 ccw(c24.869,45.461) 24.869,43.848 ccw(c24.836,45.494) 26.481,45.527 ccw(c24.902,45.528) 24.902,47.107 ccw(c24.902,45.461)
  pour cut-out: 8.736,14.35 ccw(c9.15,14.35) 9.15,13.936 ccw(c9.15,14.35) 9.564,14.35 ccw(c9.15,14.35) 9.15,14.764 ccw(c9.15,14.35)
  pour cut-out: 7.511,14.625 ccw(c7.925,14.625) 7.925,14.211 ccw(c7.925,14.625) 8.339,14.625 ccw(c7.925,14.625) 7.925,15.039 ccw(c7.925,14.625)
  region net 5V: 27,6.15 26.225,6.15 26.075,6 26.075,5.2 26.225,5.05 27,5.05 27.175,5.225 27.175,5.975
  region net 5V: 25.725,4.2 26.075,4.55 26.075,5.3 27.175,5.3 27.175,3.475 27.05,3.35 27.05,2.5 25.725,2.5
  region net 5V: 19.85,3.125 17.25,3.125 17.25,5.825 19.55,5.825 19.85,5.525 19.85,4.825 20.625,4.05
  region net 5V: 20.45,4.225 19.675,4.225 19.525,4.075 19.525,3.275 19.675,3.125 20.45,3.125 20.625,3.3 20.625,4.05
  pour cut-out: 27.137,37.35 27.137,37.625 28.263,37.625 28.263,37.35
  region net 5V: 26.95,32.375 28.025,31.3 28.025,30.375 27.95,30.3 27.1,30.3 26.95,30.45
  pour cut-out: 22.3,32.375 22.3,32.65 25.15,32.65 25.15,32.375
  region net USB_VBUS: 25.8,33.025 26.2,32.625 26.2,31.7 26.125,31.625 25.275,31.625 25.125,31.775 25.125,32.55 25.6,33.025
  region net USB_VREG: 25.1,35.75 25.45,36.1 25.825,36.1 26.175,35.75 26.175,34.825 26.05,34.725 25.275,34.725 25.1,34.9
  pour cut-out: 20.125,8.425 20.125,8.7 24.575,8.7 24.575,8.425
  pour cut-out: 23.925,13.625 23.925,13.35 19.35,13.35 19.35,13.625
  pour cut-out: 12.05,36.332 11.775,36.332 11.775,38.668 12.05,38.668
  pour cut-out: 11.325,32.375 11.325,32.65 15.725,32.65 15.725,32.375
  pour cut-out: 11.714,34.55 11.714,35.538 13.9,35.538 13.9,34.55
  pour cut-out: 15.475,37.35 15.475,37.625 26.4,37.625 26.4,37.35
  pour cut-out: 14.175,35.275 14.175,35.55 15.75,35.55 15.75,35.275
  pour cut-out: 13.989,34.45 13.989,35.7 16.325,35.7 16.325,34.45
  pour cut-out: 9.125,37.35 9.125,37.625 14.125,37.625 14.125,37.35
  region net VLDO_3V6: 4.525,15.675 4.525,16.544 4.369,16.7 3.725,16.7 3.5,16.475 3.5,15.731 3.675,15.556 4.406,15.556
  region net USB_VREG: 0.9,14.575 1.675,14.575 1.925,14.825 1.925,15.425 1.675,15.675 0.9,15.675 0.75,15.525 0.75,14.725
  region net USB_VBUS: 3.85,6.85 3.075,6.85 2.925,6.7 2.925,5.9 3.075,5.75 3.85,5.75 4,5.9 4,6.7
  region net USB_VREG: 29.525,5.65 29.575,5.7 30.375,5.7 30.875,5.2 30.875,4.525 30.738,4.388 29.612,4.387 29.525,4.475
  region net VLDO_3V6: 13.425,6.45 13.325,6.35 12.2,6.35 12.05,6.5 12.05,7.275 12.475,7.7 13.425,7.7 13.575,7.55 13.575,7.325 13.425,7.175
  pour cut-out: 6.621,13.363 6.621,13.638 12.5,13.638 12.5,13.363
  pour cut-out: 25.45,11.275 25.45,11.55 26.9,11.55 26.9,11.275
  pour cut-out: 18.125,8.725 18.125,8.45 13.675,8.45 13.675,8.725
  pour cut-out: 4.25,8.45 4.25,8.725 13.275,8.725 13.275,8.45
  region net N17783001: 12.55,5.025 12.55,5.7 12.675,5.825 15.55,5.825 15.55,4.625 15.45,4.525 13.05,4.525
  region net N17783110: 30.375,3.8 30.375,2.5 28.565,2.5 28.565,3.7 28.665,3.8
  pour cut-out: 17.075,18.85 19.325,18.85 19.325,19.225 17.075,19.225

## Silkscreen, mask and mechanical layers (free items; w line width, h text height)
Top Overlay:
  text "EFR32xG25" at 1.85,47.4 h3.2
  text "470 MHz" at 2,45 h1.9
  text "16 dBm" at 2,43 h1.9
  text "7x7 QFN56" at 2,41.025 h1.9
Bottom Overlay:
  lines w0.15: 1.1,13.8 1.1,14.25 1.275,14.425 ; 1.35,43.95 1.35,42.95 2.35,42.95 ; 1.35,47.95 1.35,48.95 2.35,48.95 ; 2.275,18.228 3.527,16.97 3.525,15.8 ; 3.526,13.951 4.498,13.949 4.675,14.125 ; 19.35,42.95 20.35,42.95 20.35,43.95 ; 19.35,48.95 20.35,48.95 20.35,47.95
  lines w0.152: 1.42,14.938 1.42,14.638 1.72,14.638 ; 1.42,15.338 1.42,15.638 1.72,15.638 ; 2.17,14.638 2.47,14.638 2.47,14.338 ; 2.42,15.538 2.42,15.638 2.67,15.638 ; 2.47,13.988 2.47,13.688 2.77,13.688 ; 3.02,13.688 3.32,13.688 3.32,13.988 ; 3.07,15.638 3.32,15.638 3.32,15.538 ; 3.225,17.95 3.225,17.65 3.525,17.65 ; 3.225,18.35 3.225,18.65 3.525,18.65 ; 3.32,14.638 3.32,14.938 ; 3.875,17.65 4.175,17.65 4.175,17.35 ; 4.175,17 4.175,16.7 4.475,16.7 ; 4.225,18.55 4.225,18.65 4.475,18.65 ; 4.875,16.7 5.175,16.7 5.175,17 ; 4.925,18.65 5.175,18.65 5.175,18.55 ; 5.175,17.65 5.175,17.95
  text "BOARD INFO" at 20.4,49.3 h1.6
  text "PAVDD / Config." at 10.15,20.025 h1.6
  text "PCB4272A Rev. A03" at 30.025,19.7 h1.52 r270
  text "VMCU" at 5.625,18.9 h1.2
  text "VMCU Config." at 0.725,17.3 h1.6 r270
  text "LDO / 3V6" at 5.45,16.85 h1.2 r270
  text "WMCU_IN" at 9.5,16.475 h1.2 r36.53
  text "USB_VREG" at -0.025,7.975 h1.2 r270
Top Solder:
  lines w0.6: 30.775,0 1.2,0 cw(c1.2,1.2) 0,1.2 0,49.8 cw(c1.2,49.8) 1.2,51 30.8,51 cw(c30.8,49.8) 32,49.8 32,1.2 cw(c30.8,1.2) 30.8,0
Bottom Solder:
  lines w0.6: 30.775,0 1.2,0 cw(c1.2,1.2) 0,1.2 0,49.8 cw(c1.2,49.8) 1.2,51 30.8,51 cw(c30.8,49.8) 32,49.8 32,1.2 cw(c30.8,1.2) 30.8,0
BOARD OUTLINE 1:
  lines w0.1: 30.775,0 1.2,0 cw(c1.2,1.2) 0,1.2 0,49.8 cw(c1.2,49.8) 1.2,51 30.8,51 cw(c30.8,49.8) 32,49.8 32,1.2 cw(c30.8,1.2) 30.8,0
Mechanical 5:
  drawing of 176 lines, arcs and shapes, not listed
  text "TP12" at 27.854,31.479 h0.5
  text "TP2" at 20.002,30.907 h0.5
  text "TP8" at 17.503,30.427 h0.5
  text "TP15" at 28.252,28.827 h0.5
  text "TP6" at 20.922,28.098 h0.5
  text "TP7" at 18.392,28.057 h0.5
  text "TP14" at 28.252,26.229 h0.5
  text "TP5" at 17.452,25.728 h0.5
  text "TP4" at 20.922,25.578 h0.5
  text "TP10" at 27.353,23.277 h0.5
  text "TP17" at 17.452,23.127 h0.5
  text "TP11" at 28.275,20.725 h0.5
  text "TP13" at 26.502,19.228 h0.5
  text "TP9" at 29.754,18.527 h0.5
  text "TP3" at 19.604,17.329 h0.5
  text "TP18" at 10.053,15.449 h0.5
  text "TP1" at 19.652,14.778 h0.5
  text "TP16" at 26.152,14.778 h0.5
  text "TP19" at 7.902,14.428 h0.5
  text "TP20" at 5.243,7.479 h0.5
Mechanical 11:
  the board outline again, w0.1
Mechanical 12:
  lines w0.1: 30.8,51 cw(c30.8,49.8) 32,49.8 32,1.2 cw(c30.8,1.2) 30.8,0 1.2,0 cw(c1.2,1.2) 0,1.2 0,49.8 cw(c1.2,49.8) 1.2,51 30.825,51
Mechanical 15:
  lines w0.025: 70.971,-42.875 71.179,-42.875 ; 71.075,-42.979 71.075,-42.771
  lines w0.1: -0.5,0 0.5,0 ; 0,-0.5 0,0.5
Mechanical 16:
  lines w0.1: -0.5,0 0.5,0 ; 0,-0.5 0,0.5
Mechanical 26:
  lines w0.2: -121.4,-34.25 -119.775,-34.25 ; -121.4,12.425 -119.775,12.425 ; -121.4,59.1 -119.775,59.1 ; -66.75,-82.5 -66.75,-80.9 ; -66.75,105.8 -66.75,107.4 ; -13.725,-82.5 -13.725,-80.9 ; -13.725,105.8 -13.725,107.4 ; 39.3,-82.5 39.3,-80.9 ; 39.3,105.8 39.3,107.4 ; 92.325,-82.5 92.325,-80.9 ; 92.325,105.8 92.325,107.4 ; 145.35,-34.225 146.975,-34.225 ; 145.35,59.125 146.975,59.125 ; 146.975,-82.5 -121.4,-82.5 -121.4,107.4 146.975,107.4 146.975,-82.475 ; -119.775,-80.9 -119.775,105.8 145.35,105.8 145.35,-80.9 -119.775,-80.9
  text "5" at -93.425,106.325 h0.5
  text "4" at -40.4,106.3 h0.5
  text "3" at 12.625,106.3 h0.5
  text "2" at 65.65,106.3 h0.5
  text "1" at 118.775,106.3 h0.5
  text "D" at 146.025,82.2 h0.5
  text "D" at -120.725,82.175 h0.5
  text "C" at 146.025,35.5 h0.5
  text "C" at -120.725,35.475 h0.5
  text "B" at 146.025,-11.175 h0.5
  text "B" at -120.725,-11.2 h0.5
  text "A" at 146.025,-57.825 h0.5
  text "A" at -120.725,-57.85 h0.5
  text "5" at -93.425,-81.975 h0.5
  text "4" at -40.4,-82 h0.5
  text "3" at 12.625,-82 h0.5
  text "2" at 65.65,-82 h0.5
  text "1" at 118.775,-82 h0.5
Mechanical 27:
  drawing of 28 lines, arcs and shapes, not listed
  text "Board Title" at 75.75,-55.95 h2.5
  text "FG25 470 MHz +16 dBm Radio Board" at 77.15,-61.5 h3.5
  text "Page Title" at 75.75,-65.675 h2.5
  text "Designed:" at 43.5,-69.425 h1.7
  text "Approved:" at 59.7,-69.425 h1.7
  text "Top Assembly" at 77.15,-69.575 h3.2
  text "TAB" at 45.025,-71.925 h2.2
  text "RGU" at 61.075,-71.925 h2.2
  text "Revision" at 133.65,-72.7 h1.7
  text "Document number" at 75.75,-72.975 h2.35
  text "Size" at 43.5,-74.175 h1.7
  text "BOM Doc. No:" at 48.425,-74.175 h1.7
  text "A03" at 133.925,-75.75 h2.7
  text "PCB4272A" at 77.15,-75.85 h3.2
  text "A4" at 44.075,-76.025 h2
  text "<>" at 49,-76.025 h2
  text "Design Created Date:" at 43.5,-78.375 h1.7
  text "Sheet Created Date:" at 75.175,-78.375 h1.7
  text "Sheet Modified Date:" at 103.6,-78.375 h1.7
  text "Sheet" at 133.65,-78.375 h1.7
  text "Monday, July 13, 2020" at 44.575,-80.325 h1.7
  text "Monday, July 13, 2020" at 76.3,-80.325 h1.7
  text "'.Print_Date'" at 104.725,-80.325 h1.7
  text "1" at 134.85,-80.325 h1.7
  text "of" at 137.975,-80.325 h1.7
  text "2" at 140.7,-80.325 h1.7
Mechanical 28:
  lines w0.2: -121.4,-34.25 -119.775,-34.25 ; -121.4,12.425 -119.775,12.425 ; -121.4,59.1 -119.775,59.1 ; -66.75,-82.5 -66.75,-80.9 ; -66.75,105.8 -66.75,107.4 ; -13.725,-82.5 -13.725,-80.9 ; -13.725,105.8 -13.725,107.4 ; 39.3,-82.5 39.3,-80.9 ; 39.3,105.8 39.3,107.4 ; 92.325,-82.5 92.325,-80.9 ; 92.325,105.8 92.325,107.4 ; 145.35,-34.225 146.975,-34.225 ; 145.35,59.125 146.975,59.125 ; 146.975,-82.5 -121.4,-82.5 -121.4,107.4 146.975,107.4 146.975,-82.475 ; -119.775,-80.9 -119.775,105.8 145.35,105.8 145.35,-80.9 -119.775,-80.9
  text "5" at -93.1,106.325 h0.5
  text "4" at -40.075,106.3 h0.5
  text "3" at 12.95,106.3 h0.5
  text "2" at 65.975,106.3 h0.5
  text "1" at 118.95,106.3 h0.5
  text "D" at 146.35,82.2 h0.5
  text "D" at -120.4,82.175 h0.5
  text "C" at 146.35,35.5 h0.5
  text "C" at -120.4,35.475 h0.5
  text "B" at 146.35,-11.175 h0.5
  text "B" at -120.4,-11.2 h0.5
  text "A" at 146.35,-57.825 h0.5
  text "A" at -120.4,-57.85 h0.5
  text "5" at -93.1,-81.975 h0.5
  text "4" at -40.075,-82 h0.5
  text "3" at 12.95,-82 h0.5
  text "2" at 65.975,-82 h0.5
  text "1" at 118.95,-82 h0.5
Mechanical 29:
  drawing of 28 lines, arcs and shapes, not listed
  text "Board Title" at -50.175,-55.95 h2.5
  text "FG25 470 MHz +16 dBm Radio Board" at -51.575,-61.5 h3.5
  text "Page Title" at -50.175,-65.675 h2.5
  text "Approved:" at -34.125,-69.425 h1.7
  text "Designed:" at -17.925,-69.425 h1.7
  text "Bottom Assembly" at -51.575,-69.575 h3.2
  text "RGU" at -35.5,-71.925 h2.2
  text "TAB" at -19.45,-71.925 h2.2
  text "Revision" at -108.075,-72.7 h1.7
  text "Document number" at -50.175,-72.975 h2.35
  text "BOM Doc. No:" at -22.85,-74.175 h1.7
  text "Size" at -17.925,-74.175 h1.7
  text "A03" at -108.339,-75.75 h2.7
  text "PCB4272A" at -51.575,-75.85 h3.2
  text "<>" at -23.425,-76.025 h2
  text "A4" at -18.5,-76.025 h2
  text "Sheet" at -108.075,-78.375 h1.7
  text "Sheet Modified Date:" at -78.025,-78.375 h1.7
  text "Sheet Created Date:" at -49.6,-78.375 h1.7
  text "Design Created Date:" at -17.925,-78.375 h1.7
  text "2" at -115.125,-80.325 h1.7
  text "of" at -112.4,-80.325 h1.7
  text "2" at -109.275,-80.325 h1.7
  text "'.Print_Date'" at -79.15,-80.325 h1.7
  text "Monday, July 13, 2020" at -50.725,-80.325 h1.7
  text "Monday, July 13, 2020" at -19,-80.325 h1.7
Mechanical 30:
  lines w0.2: -125.75,-88.975 157.75,-88.975 157.75,111.5 -125.75,111.5 -125.75,-88.975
